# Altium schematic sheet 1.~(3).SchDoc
size 420 x 297 mm
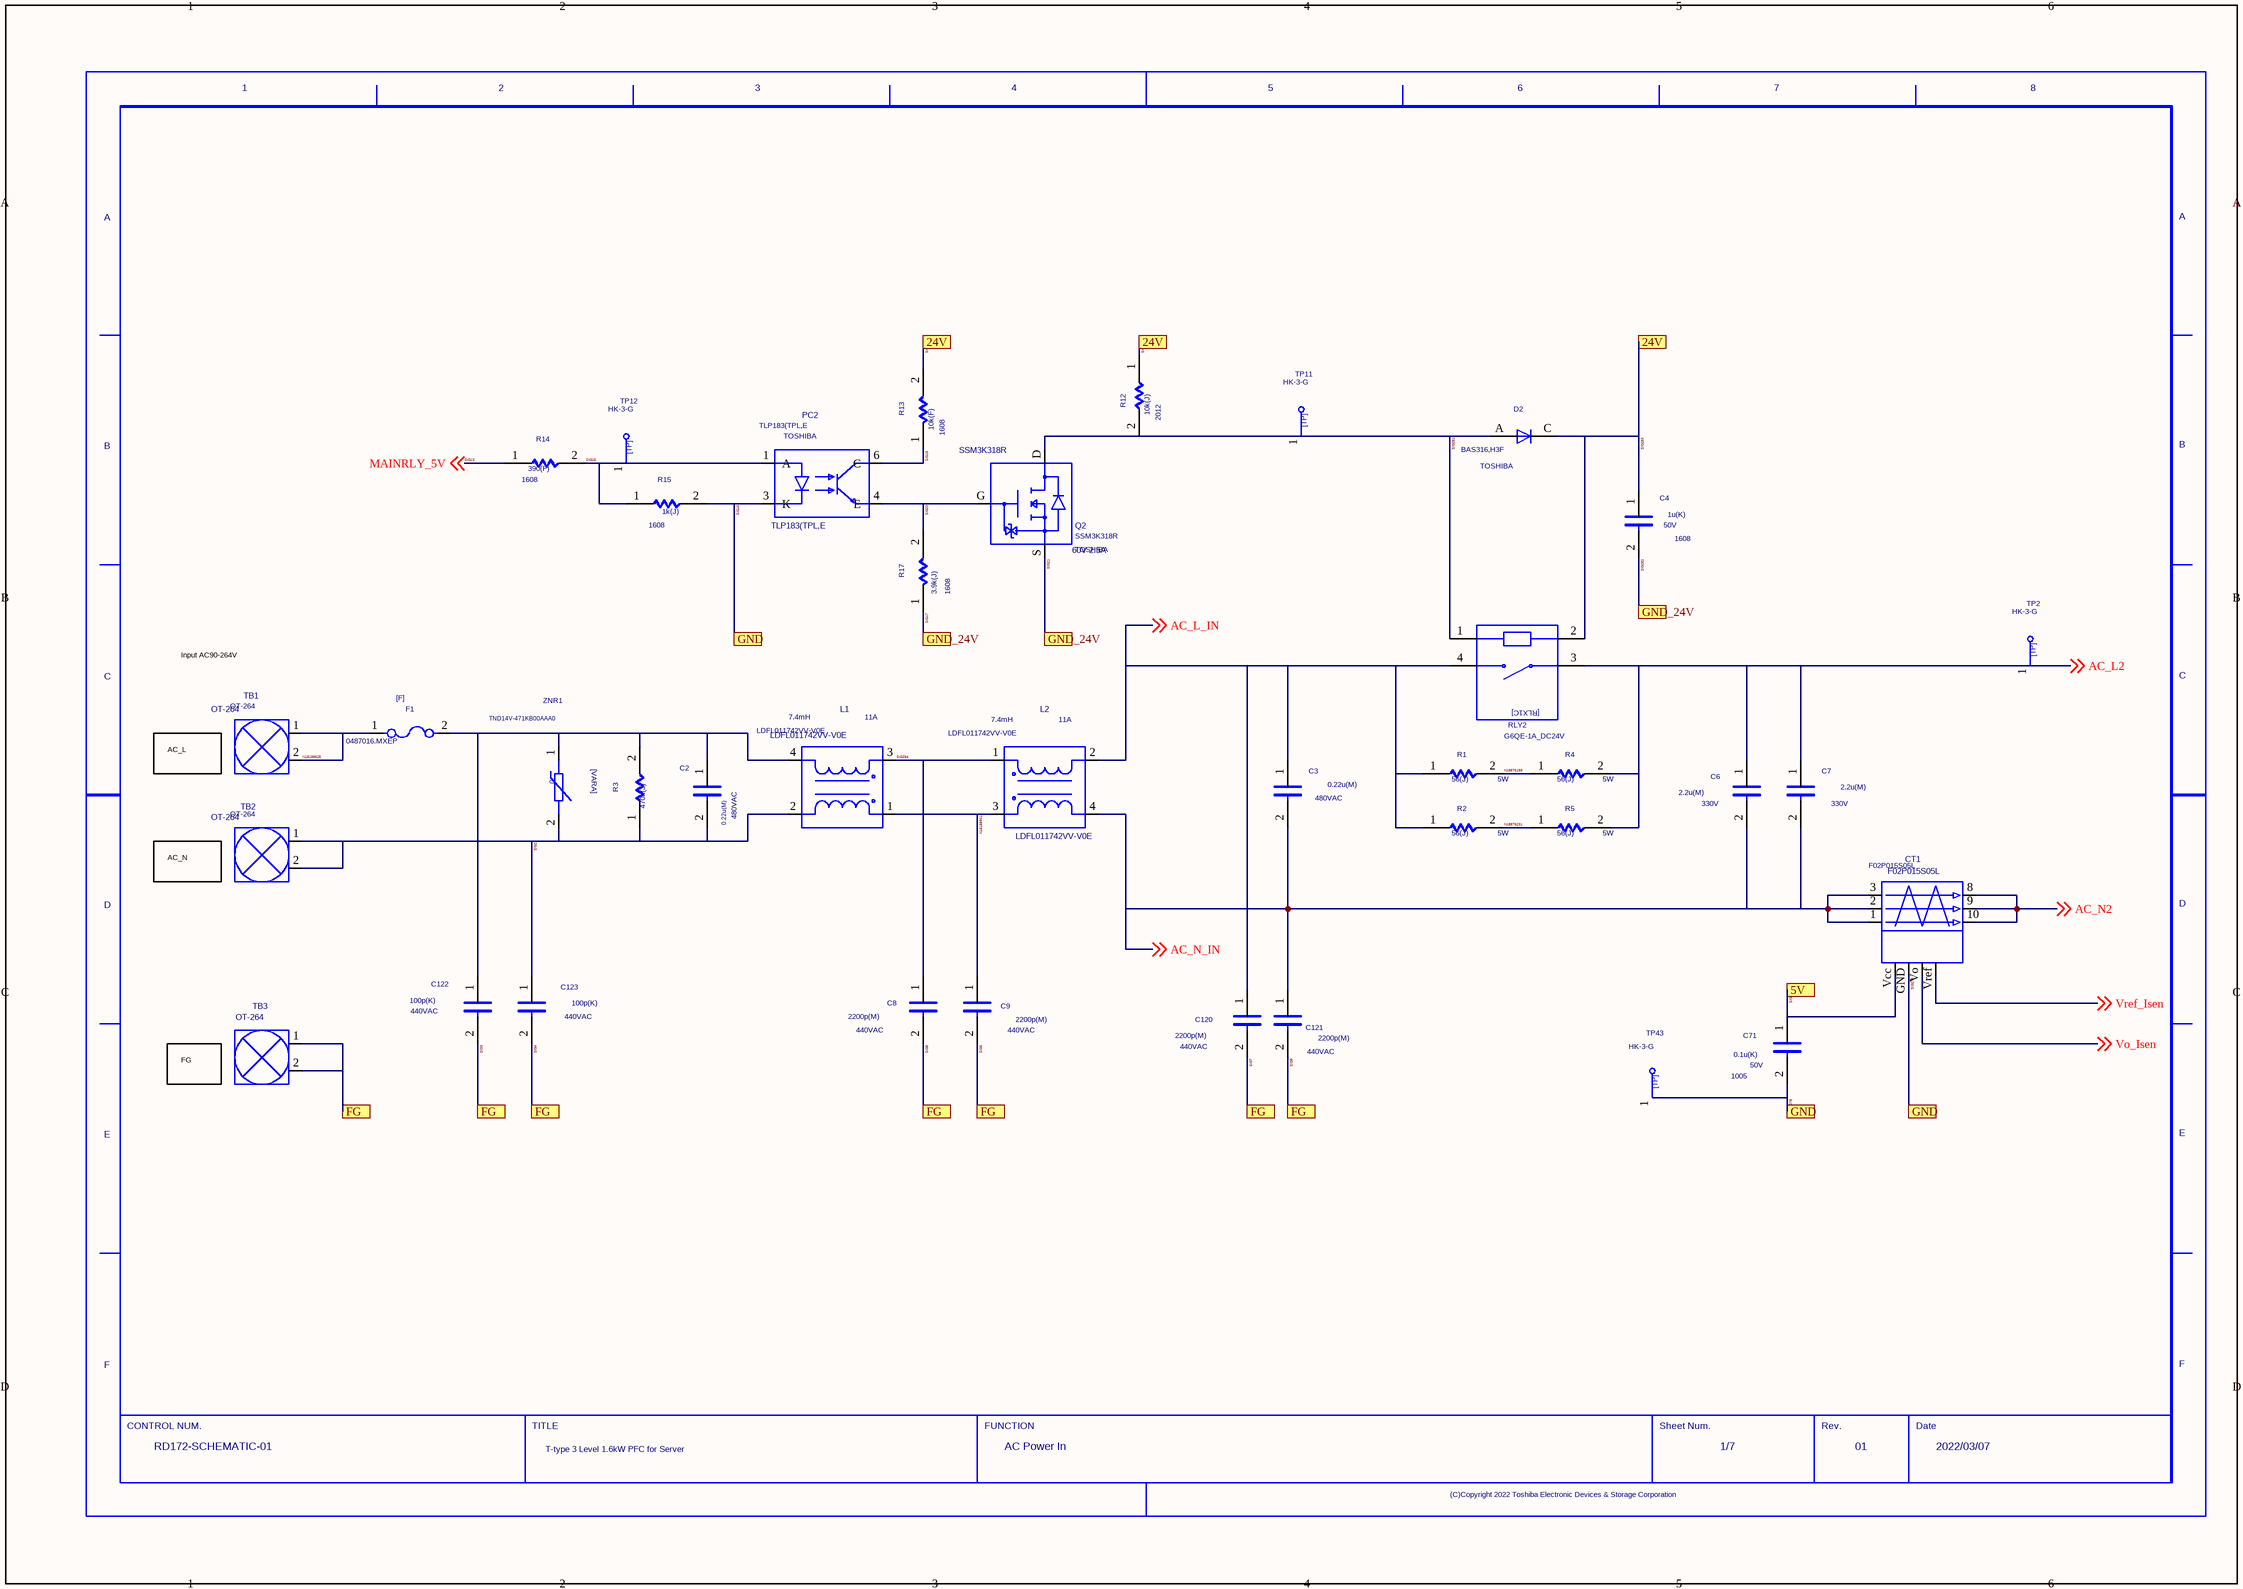
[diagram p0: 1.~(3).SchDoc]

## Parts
C2  VAL2: 480VAC  VAL1: 0.22u(M)  (hidden comment: C)
C3  VAL2: 480VAC  VAL1: 0.22u(M)  (hidden comment: C)
C4  SIZECODESMD: 1608  VAL2: 50V  VAL1: 1u(K)  (hidden comment: C)
C6  VAL2: 330V  VAL1: 2.2u(M)  (hidden comment: C)
C7  VAL2: 330V  VAL1: 2.2u(M)  (hidden comment: C)
C8  VAL2: 440VAC  VAL1: 2200p(M)  (hidden comment: C)
C9  VAL2: 440VAC  VAL1: 2200p(M)  (hidden comment: C)
C71  SIZECODESMD: 1005  VAL2: 50V  VAL1: 0.1u(K)  (hidden comment: C)
C120  VAL2: 440VAC  VAL1: 2200p(M)  (hidden comment: C)
C121  VAL2: 440VAC  VAL1: 2200p(M)  (hidden comment: C)
C122  VAL2: 440VAC  VAL1: 100p(K)  (hidden comment: C)
C123  VAL2: 440VAC  VAL1: 100p(K)  (hidden comment: C)
CT1  F02P015S05L
D2  VAL3: BAS316,H3F  USERCOMPTEXT3: TOSHIBA  (hidden comment: D)
F1  VAL3: 0487016.MXEP  (hidden comment: F)
L1  LDFL011742VV-V0E  VAL1: 7.4mH
L2  LDFL011742VV-V0E  VAL1: 7.4mH
PC2  TLP183(TPL,E  USERCOMPTEXT3: TOSHIBA
Q2  SSM3K318R  NOTE: 60V 2.5A  USERCOMPTEXT3: TOSHIBA
R1  VAL2: 5W  VAL1: 56(J)  (hidden comment: R)
R2  VAL2: 5W  VAL1: 56(J)  (hidden comment: R)
R3  VAL1: 470k(J)  (hidden comment: R)
R4  VAL2: 5W  VAL1: 56(J)  (hidden comment: R)
R5  VAL2: 5W  VAL1: 56(J)  (hidden comment: R)
R12  SIZECODESMD: 2012  VAL1: 10k(J)  (hidden comment: R)
R13  SIZECODESMD: 1608  VAL1: 10k(F)  (hidden comment: R)
R14  SIZECODESMD: 1608  VAL1: 390(F)  (hidden comment: R)
R15  SIZECODESMD: 1608  VAL1: 1k(J)  (hidden comment: R)
R17  SIZECODESMD: 1608  VAL1: 3.9k(J)  (hidden comment: R)
RLY2  VAL3: G6QE-1A_DC24V  (hidden comment: RLX1C)
TB1  OT-264
TB2  OT-264
TB3  OT-264
TP2  VAL3: HK-3-G  (hidden comment: TP)
TP11  VAL3: HK-3-G  (hidden comment: TP)
TP12  VAL3: HK-3-G  (hidden comment: TP)
TP43  VAL3: HK-3-G  (hidden comment: TP)
U?  DATE: 2022/03/07  DRAWINGNUMBER: RD172-SCHEMATIC-01  REVISION: 01  SHEETNUMBER: 1/7  TITLE: T-type 3 Level 1.6kW PFC for Server  FUNCTION: AC Power In  (hidden comment: WAKU_DEF100)
ZNR1  VAL3: TND14V-471KB00AAA0  (hidden comment: VARA)

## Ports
5V, 24V, FG, GND, GND_24V

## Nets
AC_L2: C6.1 C7.1 R4.2 R5.2 RLY2.3 TP2.1 ; off-sheet AC_L2
AC_L_IN: C3.1 C120.1 L2.2 R1.1 R2.1 RLY2.4 ; off-sheet AC_L_IN
AC_N2: CT1.8 CT1.9 CT1.10 ; off-sheet AC_N2
AC_N_IN: C3.2 C6.2 C7.2 C121.1 CT1.1 CT1.2 CT1.3 L2.4 ; off-sheet AC_N_IN
N18188625: F1.1 TB1.1 TB1.2
N18188901: C9.1 L1.1 L2.3
N18876199: R1.2 R4.1
N18876231: R2.2 R5.1
SIG1: C2.1 C122.1 F1.2 L1.4 R3.2 ZNR1.1
SIG2: C2.2 C123.1 L1.2 R3.1 TB2.1 TB2.2 ZNR1.2
SIG3: C8.2 C9.2 C120.2 C121.2 C122.2 C123.2 TB3.1 TB3.2 ; port FG  [also labelled SIG4, SIG5, SIG6, SIG7, SIG8]
SIG13: R14.1 ; off-sheet MAINRLY_5V  [also labelled MAINRLY_5V]
SIG15: PC2.1(A) R14.2 R15.1 TP12.1
SIG16: C71.2 CT1.GND PC2.3(K) R15.2 TP43.1 ; port GND  [also labelled SIG275, SIG278]
SIG17: C4.2 Q2.S R17.1 ; port GND_24V  [also labelled SIG21, SIG282]
SIG18: C4.1 D2.C R12.1 R13.2 RLY2.2 ; port 24V  [also labelled SIG22, SIG283]
SIG19: PC2.6(C) R13.1
SIG20: PC2.4(E) Q2.G R17.2
SIG277: C71.1 CT1.Vcc(VCC) ; port 5V
SIG281: D2.A Q2.D R12.2 RLY2.1 TP11.1
SIG284: C8.1 L1.3 L2.1
Vo_Isen: CT1.Vo ; off-sheet Vo_Isen
Vref_Isen: CT1.Vref ; off-sheet Vref_Isen

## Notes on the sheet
- Input AC90-264V
- AC_L
- AC_N
- FG

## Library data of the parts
C2 C3 = C: OriginalSymbolOrigin: (2540,7620); COMP: -C-F339X142248MIP2T0
C4 = C: OriginalSymbolOrigin: (2540,7620); COMP: -C-UMK107AB7105KA-T
C6 C7 = C: OriginalSymbolOrigin: (2540,7620); COMP: -C-B32914A3225M000
C8 C9 C120 C121 = C: OriginalSymbolOrigin: (2540,7620); COMP: -C-CD45-E2GA222M-VKA
C71 = C: OriginalSymbolOrigin: (2540,7620); COMP: -C-UMK105BJ104KV-F
C122 C123 = C: OriginalSymbolOrigin: (2540,7620); COMP: -C-CD45-B2GA101K-VKA
CT1 = F02P015S05L: Current Transducer, 15A; MANUFACTURER: Tamura; COMP: -CT-F02P015S05L_PIN; TIME: 16:53:55; UPDATEUSER: t5459927; UPDATETIME: 16:08:01; SAVECOUNT: 2; SAVEAREA0: -5739,-18135,20354,994; OriginalSymbolOrigin: (0,0)
D2 = D: SAVEAREA0: -225,-91,12804,7836; SAVECOUNT: 3; TIME: 14:49:55; UPDATEUSER: 19870035; UPDATETIME: 14:20:16; OriginalSymbolOrigin: (5080,5080); COMP: -D-BAS316_H3F_AC
F1 = F: OriginalSymbolOrigin: (2540,5080); COMP: -F-0487016MXEP
L1 L2 = LDFL011742VV_V0E: 11A; MANUFACTURER: Nippon Chemi-Con; COMP: -L-LDFL011742VV-V0E; TIME: 16:53:58; UPDATEUSER: t5459927; SAVECOUNT: 1; SAVEAREA0: -3836,-15544,18528,852; OriginalSymbolOrigin: (0,0); INSTANCENAME: INS18188789
PC2 = TLP183_TPL_E: Photocoupler; COMP: -PC-TLP183_TPL_E; TIME: 16:53:54; UPDATEUSER: t5459927; UPDATETIME: 16:20:20; SAVECOUNT: 2; SAVEAREA0: -3467,-14897,20665,2795; OriginalSymbolOrigin: (0,0)
Q2 = SSM3K318R: MOSFET; COMP: -Q-SSM3K318R_LF; TIME: 16:53:56; UPDATEUSER: t5459927; UPDATETIME: 14:46:06; SAVECOUNT: 2; SAVEAREA0: -8920,-18190,20901,3672; OriginalSymbolOrigin: (0,0)
R1 R2 R4 R5 = R: OriginalSymbolOrigin: (5080,5080); COMP: -R-SQMW556RJ
R3 = R: OriginalSymbolOrigin: (5080,5080); VAL2: 1W; COMP: -R-RCR60C474J
R12 = R: OriginalSymbolOrigin: (5080,5080); COMP: -R-RK73B2ATTD103J; VAL2: 250mW
R13 = R: OriginalSymbolOrigin: (5080,5080); COMP: -R-ERJ3EKF1002V; VAL2: 100mW
R14 = R: OriginalSymbolOrigin: (5080,5080); COMP: -R-ERJ3EKF3900V; VAL2: 100mW
R15 = R: OriginalSymbolOrigin: (5080,5080); COMP: -R-RK73B1JTTD102J; VAL2: 125mW
R17 = R: OriginalSymbolOrigin: (5080,5080); COMP: -R-RK73B1JTTD392J; VAL2: 100mW
RLY2 = RLX1C: SAVECOUNT: 9; SAVEAREA0: -9347,-440,34039,23986; OriginalSymbolOrigin: (5080,20320); COMP: -RL-G6QE-1A_DC24
TB1 = OT_264: Terminal, 50A, M4; MANUFACTURER: Osada; COMP: -TB-OT-264; TIME: 16:53:54; UPDATEUSER: t5459927; SAVECOUNT: 1; SAVEAREA0: -3825,-10384,11084,546; OriginalSymbolOrigin: (0,0); REFERENCE TEMPLATE: TB; INSTANCENAME: INS18188586
TB2 = OT_264: Terminal, 50A, M4; MANUFACTURER: Osada; COMP: -TB-OT-264; TIME: 16:53:54; UPDATEUSER: t5459927; SAVECOUNT: 1; SAVEAREA0: -3825,-10384,11084,546; OriginalSymbolOrigin: (0,0); REFERENCE TEMPLATE: TB; INSTANCENAME: INS18188886
TB3 = OT_264: Terminal, 50A, M4; MANUFACTURER: Osada; COMP: -TB-OT-264; TIME: 16:53:54; UPDATEUSER: t5459927; UPDATETIME: 16:17:50; SAVECOUNT: 2; SAVEAREA0: -3825,-10384,11084,546; OriginalSymbolOrigin: (0,0)
TP2 TP11 TP12 TP43 = TP: TIME: 16:12:21; UPDATEUSER: fukuda-y; UPDATETIME: 16:18:11; SAVECOUNT: 2; SAVEAREA0: -242,-92,12810,7836; OriginalSymbolOrigin: (0,7620); COMP: -TP-HK-3-G
U? = WAKU_DEF100: PLOTTIME: HH:MM; SAVEAREA0: 148187,-66180,486823,89919; TIME: 14:30:25; UPDATEUSER: t5459927; UPDATETIME: 09:34:25; SAVECOUNT: 6; OriginalSymbolOrigin: (10160,284480)
ZNR1 = VARA: SAVEAREA0: -9950,-8554,25168,13619; SAVECOUNT: 12; TIME: 09:56:50; UPDATEUSER: tomizawa-y; OriginalSymbolOrigin: (2540,5080); COMP: -ZNR-TND14V-471KB00AAA0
